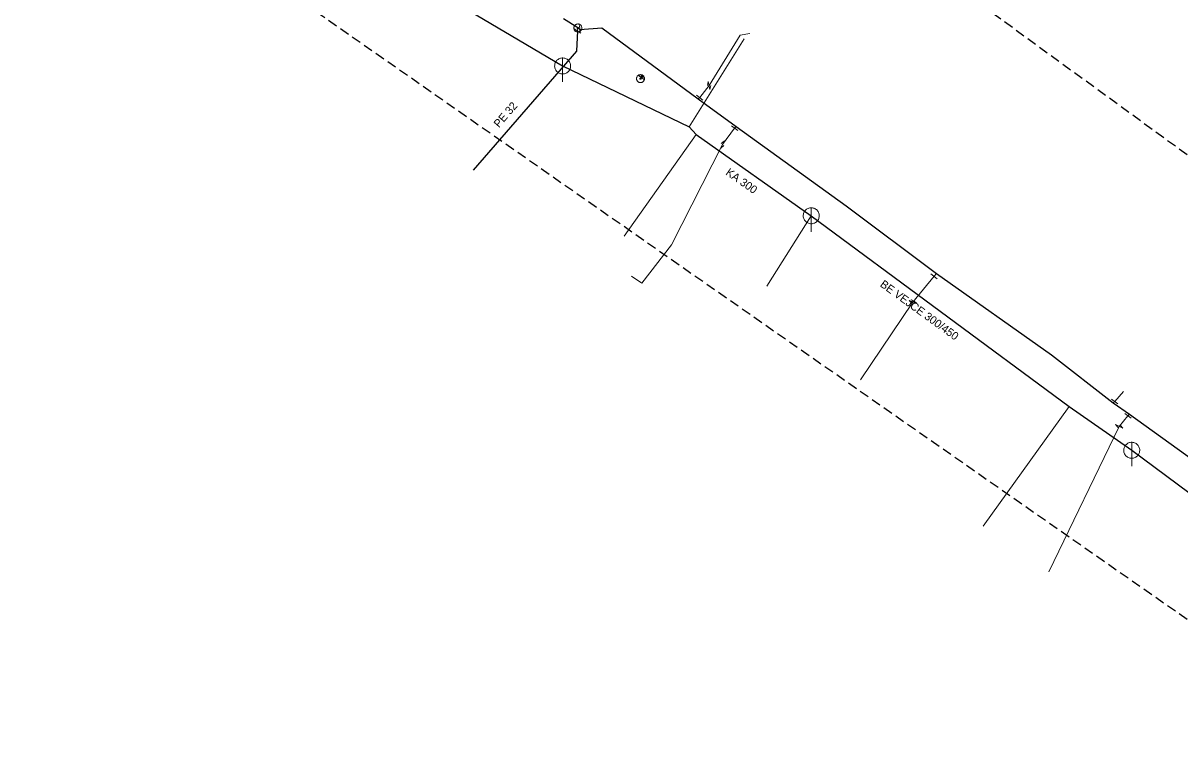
# Model space of a CAD drawing. Extents: x -749365 to -748625, y -965388 to -964881.
# Drawn here: x -748913.9 to -748769.4, y -965278.6 to -965189.7 of the extents above; entities that cross this region are included whole.
import ezdxf

# ---------------------------------------------------------------- set-up
doc = ezdxf.new("R2010")
doc.units = 0
doc.header["$LTSCALE"] = 0.4
doc.linetypes.add('MEDIUM_DASHED', pattern=[4.5, 3, -1.5])
for name, color, linetype, lineweight in [('1', 7, 'MEDIUM_DASHED', 25), ('11', 7, 'Continuous', 13), ('13', 7, 'Continuous', 13), ('14', 7, 'Continuous', 13), ('17', 7, 'Continuous', 25), ('22', 7, 'Continuous', 13), ('34', 7, 'Continuous', 13), ('47', 7, 'Continuous', 13), ('9', 7, 'Continuous', 13)]:
    doc.layers.add(name, color=color, linetype=linetype, lineweight=lineweight)

msp = doc.modelspace()

# ---------------------------------------------------------------- linework, layer by layer
at = {"layer": '1'}
for points in [[(-748843.645, -965151.367), (-748721.639, -965240.188)], [(-748747.771, -965278.626), (-748913.896, -965162.751)]]:
    msp.add_lwpolyline(points, dxfattribs=at)
at = {"layer": '11'}
for p, q in [((-748823.791, -965191.665), (-748830.686, -965202.653)), ((-748838.795, -965216.31), (-748829.791, -965203.589)), ((-748820.944, -965222.563), (-748815.417, -965213.762)), ((-748793.92, -965252.532), (-748783.169, -965237.599))]:
    msp.add_line(p, q, dxfattribs=at)
at = {"layer": '13'}
for p, q in [((-748829.35, -965198.989), (-748828.179, -965197.5)), ((-748824.986, -965202.824), (-748826.493, -965204.862)), ((-748800.07, -965221.322), (-748802.701, -965224.546)), ((-748802.701, -965224.546), (-748809.269, -965234.274)), ((-748777.5, -965236.96), (-748776.412, -965235.719)), ((-748775.84, -965238.756), (-748776.945, -965240.074)), ((-748776.945, -965240.074), (-748785.718, -965258.253))]:
    msp.add_line(p, q, dxfattribs=at)
for points in [[(-748828.179, -965197.5), (-748824.315, -965191.195), (-748823.096, -965190.973)], [(-748826.493, -965204.862), (-748832.894, -965217.38), (-748836.567, -965222.187), (-748837.857, -965221.327)]]:
    msp.add_lwpolyline(points, dxfattribs=at)
at = {"layer": '14', "lineweight": 25}
msp.add_line((-748900.66, -965162.96), (-748846.48, -965195.039), dxfattribs=at)
at = {"layer": '14'}
for p, q in [((-748844.578, -965190.3), (-748844.618, -965190.673)), ((-748844.578, -965190.3), (-748844.32, -965190.469)), ((-748836.754, -965196.63), (-748836.64, -965196.486)), ((-748836.64, -965196.486), (-748836.522, -965196.337)), ((-748829.535, -965199.166), (-748829.35, -965198.989)), ((-748824.8, -965202.6), (-748824.986, -965202.824)), ((-748799.78, -965220.98), (-748800.07, -965221.322)), ((-748777.69, -965237.149), (-748777.5, -965236.96)), ((-748775.66, -965238.539), (-748775.84, -965238.756))]:
    msp.add_line(p, q, dxfattribs=at)
at = {"layer": '14', "lineweight": 25}
for points in [[(-748846.48, -965195.039), (-748830.686, -965202.653), (-748829.791, -965203.589), (-748815.416, -965213.761)], [(-748815.416, -965213.761), (-748783.169, -965237.598), (-748775.37, -965243.07), (-748733.398, -965274.196)]]:
    msp.add_lwpolyline(points, dxfattribs=at)
at = {"layer": '17'}
msp.add_line((-748844.578, -965190.3), (-748846.378, -965189.157), dxfattribs=at)
for points in [[(-748844.618, -965190.673), (-748844.769, -965193.182), (-748857.681, -965208.058)], [(-748844.32, -965190.469), (-748841.57, -965190.28), (-748829.535, -965199.166), (-748824.8, -965202.6), (-748811.05, -965212.52), (-748799.78, -965220.98), (-748785.41, -965231.14), (-748777.69, -965237.149), (-748775.66, -965238.539), (-748746.309, -965259.66), (-748736.25, -965266.93)]]:
    msp.add_lwpolyline(points, dxfattribs=at)
at = {"layer": '22'}
for p, q in [((-748846.48, -965197.039), (-748846.479, -965194.039)), ((-748815.416, -965215.761), (-748815.415, -965212.761)), ((-748775.37, -965245.07), (-748775.369, -965242.07))]:
    msp.add_line(p, q, dxfattribs=at)
for points in [[(-748845.48, -965195.039), (-748845.485, -965194.93), (-748845.503, -965194.822), (-748845.533, -965194.716), (-748845.573, -965194.615), (-748845.625, -965194.518), (-748845.687, -965194.428), (-748845.759, -965194.345), (-748845.839, -965194.271), (-748845.927, -965194.205), (-748846.021, -965194.15), (-748846.121, -965194.105), (-748846.226, -965194.072), (-748846.333, -965194.05), (-748846.442, -965194.04), (-748846.552, -965194.042), (-748846.66, -965194.056), (-748846.767, -965194.081), (-748846.87, -965194.118), (-748846.968, -965194.167), (-748847.06, -965194.225), (-748847.146, -965194.294), (-748847.223, -965194.371), (-748847.292, -965194.457), (-748847.351, -965194.549), (-748847.399, -965194.647), (-748847.436, -965194.75), (-748847.462, -965194.857), (-748847.476, -965194.965), (-748847.479, -965195.075), (-748847.469, -965195.184), (-748847.448, -965195.291), (-748847.414, -965195.395), (-748847.37, -965195.495), (-748847.315, -965195.59), (-748847.249, -965195.678), (-748847.175, -965195.758), (-748847.092, -965195.83), (-748847.002, -965195.892), (-748846.906, -965195.944), (-748846.804, -965195.985), (-748846.699, -965196.015), (-748846.591, -965196.033), (-748846.481, -965196.039), (-748846.372, -965196.033), (-748846.264, -965196.015), (-748846.159, -965195.986), (-748846.057, -965195.945), (-748845.96, -965195.893), (-748845.87, -965195.831), (-748845.787, -965195.76), (-748845.712, -965195.68), (-748845.647, -965195.592), (-748845.591, -965195.498), (-748845.547, -965195.398), (-748845.513, -965195.294), (-748845.491, -965195.186), (-748845.481, -965195.077)], [(-748814.416, -965213.761), (-748814.421, -965213.652), (-748814.439, -965213.544), (-748814.469, -965213.438), (-748814.509, -965213.337), (-748814.561, -965213.24), (-748814.623, -965213.15), (-748814.695, -965213.067), (-748814.775, -965212.993), (-748814.863, -965212.927), (-748814.957, -965212.872), (-748815.057, -965212.827), (-748815.162, -965212.794), (-748815.269, -965212.772), (-748815.378, -965212.762), (-748815.488, -965212.764), (-748815.596, -965212.778), (-748815.703, -965212.803), (-748815.806, -965212.84), (-748815.904, -965212.889), (-748815.996, -965212.947), (-748816.082, -965213.016), (-748816.159, -965213.093), (-748816.228, -965213.179), (-748816.287, -965213.271), (-748816.335, -965213.369), (-748816.372, -965213.472), (-748816.398, -965213.579), (-748816.412, -965213.687), (-748816.415, -965213.797), (-748816.405, -965213.906), (-748816.384, -965214.013), (-748816.35, -965214.117), (-748816.306, -965214.217), (-748816.251, -965214.312), (-748816.185, -965214.4), (-748816.111, -965214.48), (-748816.028, -965214.552), (-748815.938, -965214.614), (-748815.842, -965214.666), (-748815.74, -965214.707), (-748815.635, -965214.737), (-748815.527, -965214.755), (-748815.417, -965214.761), (-748815.308, -965214.755), (-748815.2, -965214.737), (-748815.095, -965214.708), (-748814.993, -965214.667), (-748814.896, -965214.615), (-748814.806, -965214.553), (-748814.723, -965214.482), (-748814.648, -965214.402), (-748814.583, -965214.314), (-748814.527, -965214.22), (-748814.483, -965214.12), (-748814.449, -965214.016), (-748814.427, -965213.908), (-748814.417, -965213.799)], [(-748774.37, -965243.07), (-748774.375, -965242.961), (-748774.393, -965242.853), (-748774.423, -965242.747), (-748774.463, -965242.646), (-748774.515, -965242.549), (-748774.577, -965242.459), (-748774.649, -965242.376), (-748774.729, -965242.302), (-748774.817, -965242.236), (-748774.911, -965242.181), (-748775.011, -965242.136), (-748775.116, -965242.103), (-748775.223, -965242.081), (-748775.332, -965242.071), (-748775.442, -965242.073), (-748775.55, -965242.087), (-748775.657, -965242.112), (-748775.76, -965242.149), (-748775.858, -965242.198), (-748775.95, -965242.256), (-748776.036, -965242.325), (-748776.113, -965242.402), (-748776.182, -965242.488), (-748776.241, -965242.58), (-748776.289, -965242.678), (-748776.326, -965242.781), (-748776.352, -965242.888), (-748776.366, -965242.996), (-748776.369, -965243.106), (-748776.359, -965243.215), (-748776.338, -965243.322), (-748776.304, -965243.426), (-748776.26, -965243.526), (-748776.205, -965243.621), (-748776.139, -965243.709), (-748776.065, -965243.789), (-748775.982, -965243.861), (-748775.892, -965243.923), (-748775.796, -965243.975), (-748775.694, -965244.016), (-748775.589, -965244.046), (-748775.481, -965244.064), (-748775.371, -965244.07), (-748775.262, -965244.064), (-748775.154, -965244.046), (-748775.049, -965244.017), (-748774.947, -965243.976), (-748774.85, -965243.924), (-748774.76, -965243.862), (-748774.677, -965243.791), (-748774.602, -965243.711), (-748774.537, -965243.623), (-748774.481, -965243.529), (-748774.437, -965243.429), (-748774.403, -965243.325), (-748774.381, -965243.217), (-748774.371, -965243.108)]]:
    msp.add_lwpolyline(points, close=True, dxfattribs=at)
at = {"layer": '34'}
for p, q in [((-748844.203, -965190.952), (-748845.032, -965190.392)), ((-748844.354, -965189.97), (-748844.286, -965190.967)), ((-748837.042, -965196.188), (-748836.238, -965196.783)), ((-748829.743, -965198.68), (-748828.957, -965199.298)), ((-748824.583, -965203.12), (-748825.387, -965202.526)), ((-748799.682, -965221.637), (-748800.457, -965221.005)), ((-748777.905, -965236.667), (-748777.094, -965237.252)), ((-748775.432, -965239.045), (-748776.246, -965238.465))]:
    msp.add_line(p, q, dxfattribs=at)
at = {"layer": '47'}
for p, q in [((-748828.277, -965197), (-748828.38, -965197.5)), ((-748826.27, -965204.403), (-748826.653, -965204.741)), ((-748802.231, -965224.744), (-748802.588, -965224.379)), ((-748776.499, -965240.32), (-748776.815, -965239.92))]:
    msp.add_line(p, q, dxfattribs=at)
for points in [[(-748844.857, -965190.714), (-748844.813, -965190.74), (-748844.765, -965190.763), (-748844.716, -965190.779), (-748844.665, -965190.792), (-748844.613, -965190.798), (-748844.56, -965190.799), (-748844.508, -965190.794), (-748844.457, -965190.784), (-748844.407, -965190.769), (-748844.359, -965190.749), (-748844.312, -965190.724), (-748844.27, -965190.693), (-748844.231, -965190.659), (-748844.195, -965190.621), (-748844.163, -965190.579), (-748844.137, -965190.535), (-748844.114, -965190.487), (-748844.097, -965190.437), (-748844.085, -965190.387), (-748844.079, -965190.335), (-748844.078, -965190.282), (-748844.083, -965190.23), (-748844.092, -965190.178), (-748844.107, -965190.128), (-748844.128, -965190.081), (-748844.153, -965190.034), (-748844.183, -965189.991), (-748844.218, -965189.953), (-748844.256, -965189.917), (-748844.298, -965189.885), (-748844.342, -965189.859), (-748844.39, -965189.836), (-748844.439, -965189.818), (-748844.49, -965189.807), (-748844.542, -965189.801), (-748844.594, -965189.799), (-748844.647, -965189.804), (-748844.698, -965189.814), (-748844.749, -965189.829), (-748844.796, -965189.85), (-748844.843, -965189.875), (-748844.885, -965189.905), (-748844.924, -965189.94), (-748844.96, -965189.978), (-748844.992, -965190.02), (-748845.018, -965190.064), (-748845.041, -965190.112), (-748845.058, -965190.161), (-748845.07, -965190.212), (-748845.076, -965190.264), (-748845.078, -965190.316), (-748845.073, -965190.368), (-748845.063, -965190.419), (-748845.047, -965190.47), (-748845.027, -965190.518), (-748845.002, -965190.565), (-748844.972, -965190.606), (-748844.937, -965190.646), (-748844.899, -965190.682)], [(-748844.623, -965190.367), (-748844.616, -965190.372), (-748844.608, -965190.375), (-748844.6, -965190.378), (-748844.592, -965190.38), (-748844.583, -965190.381), (-748844.575, -965190.381), (-748844.566, -965190.381), (-748844.558, -965190.379), (-748844.55, -965190.376), (-748844.542, -965190.373), (-748844.534, -965190.369), (-748844.527, -965190.364), (-748844.521, -965190.358), (-748844.515, -965190.353), (-748844.51, -965190.345), (-748844.505, -965190.338), (-748844.502, -965190.33), (-748844.499, -965190.322), (-748844.497, -965190.314), (-748844.496, -965190.305), (-748844.496, -965190.297), (-748844.496, -965190.288), (-748844.498, -965190.28), (-748844.5, -965190.271), (-748844.504, -965190.264), (-748844.508, -965190.256), (-748844.513, -965190.249), (-748844.519, -965190.243), (-748844.524, -965190.237), (-748844.532, -965190.232), (-748844.539, -965190.227), (-748844.547, -965190.224), (-748844.555, -965190.221), (-748844.563, -965190.219), (-748844.572, -965190.218), (-748844.58, -965190.217), (-748844.589, -965190.218), (-748844.597, -965190.22), (-748844.606, -965190.222), (-748844.613, -965190.226), (-748844.621, -965190.23), (-748844.628, -965190.235), (-748844.634, -965190.241), (-748844.64, -965190.246), (-748844.645, -965190.254), (-748844.65, -965190.261), (-748844.653, -965190.269), (-748844.656, -965190.277), (-748844.658, -965190.285), (-748844.659, -965190.294), (-748844.66, -965190.302), (-748844.659, -965190.311), (-748844.657, -965190.319), (-748844.654, -965190.327), (-748844.651, -965190.335), (-748844.647, -965190.343), (-748844.642, -965190.35), (-748844.636, -965190.356), (-748844.631, -965190.362)], [(-748836.35, -965196.925), (-748836.322, -965196.881), (-748836.297, -965196.834), (-748836.279, -965196.786), (-748836.265, -965196.736), (-748836.256, -965196.683), (-748836.254, -965196.631), (-748836.257, -965196.579), (-748836.265, -965196.527), (-748836.278, -965196.477), (-748836.296, -965196.428), (-748836.32, -965196.381), (-748836.349, -965196.337), (-748836.381, -965196.296), (-748836.418, -965196.259), (-748836.458, -965196.226), (-748836.502, -965196.198), (-748836.549, -965196.173), (-748836.598, -965196.155), (-748836.647, -965196.141), (-748836.7, -965196.132), (-748836.752, -965196.13), (-748836.805, -965196.132), (-748836.856, -965196.14), (-748836.907, -965196.153), (-748836.955, -965196.172), (-748837.002, -965196.196), (-748837.047, -965196.224), (-748837.087, -965196.257), (-748837.124, -965196.294), (-748837.157, -965196.334), (-748837.185, -965196.378), (-748837.21, -965196.425), (-748837.229, -965196.474), (-748837.242, -965196.523), (-748837.251, -965196.576), (-748837.254, -965196.628), (-748837.252, -965196.68), (-748837.244, -965196.732), (-748837.23, -965196.783), (-748837.211, -965196.831), (-748837.187, -965196.878), (-748837.16, -965196.922), (-748837.126, -965196.963), (-748837.089, -965197), (-748837.049, -965197.033), (-748837.005, -965197.061), (-748836.958, -965197.086), (-748836.91, -965197.105), (-748836.86, -965197.118), (-748836.807, -965197.127), (-748836.755, -965197.13), (-748836.704, -965197.127), (-748836.652, -965197.119), (-748836.601, -965197.105), (-748836.552, -965197.087), (-748836.505, -965197.063), (-748836.462, -965197.035), (-748836.42, -965197.002), (-748836.383, -965196.965)], [(-748836.687, -965196.678), (-748836.682, -965196.671), (-748836.679, -965196.663), (-748836.676, -965196.655), (-748836.673, -965196.647), (-748836.672, -965196.638), (-748836.672, -965196.63), (-748836.672, -965196.621), (-748836.673, -965196.613), (-748836.676, -965196.605), (-748836.678, -965196.596), (-748836.683, -965196.588), (-748836.687, -965196.581), (-748836.693, -965196.575), (-748836.698, -965196.569), (-748836.705, -965196.563), (-748836.712, -965196.558), (-748836.72, -965196.555), (-748836.728, -965196.552), (-748836.736, -965196.549), (-748836.745, -965196.548), (-748836.753, -965196.548), (-748836.762, -965196.548), (-748836.77, -965196.549), (-748836.779, -965196.551), (-748836.787, -965196.554), (-748836.795, -965196.559), (-748836.802, -965196.563), (-748836.808, -965196.569), (-748836.814, -965196.574), (-748836.82, -965196.581), (-748836.825, -965196.588), (-748836.828, -965196.596), (-748836.831, -965196.604), (-748836.834, -965196.612), (-748836.835, -965196.621), (-748836.836, -965196.629), (-748836.835, -965196.638), (-748836.834, -965196.646), (-748836.832, -965196.655), (-748836.829, -965196.663), (-748836.824, -965196.671), (-748836.82, -965196.678), (-748836.814, -965196.684), (-748836.809, -965196.69), (-748836.802, -965196.696), (-748836.795, -965196.701), (-748836.787, -965196.704), (-748836.779, -965196.707), (-748836.771, -965196.71), (-748836.762, -965196.711), (-748836.754, -965196.712), (-748836.745, -965196.711), (-748836.737, -965196.71), (-748836.729, -965196.707), (-748836.72, -965196.705), (-748836.712, -965196.7), (-748836.705, -965196.696), (-748836.699, -965196.69), (-748836.693, -965196.685)]]:
    msp.add_lwpolyline(points, close=True, dxfattribs=at)
for points in [[(-748828.277, -965197), (-748828.081, -965198), (-748827.978, -965197.5)], [(-748826.27, -965204.403), (-748826.715, -965205.32), (-748826.332, -965204.982)], [(-748802.231, -965224.744), (-748803.17, -965224.347), (-748802.813, -965224.712)], [(-748776.499, -965240.32), (-748777.39, -965239.827), (-748777.074, -965240.227)]]:
    msp.add_lwpolyline(points, dxfattribs=at)
at = {"layer": '9'}
for points in [[(-748836.648, -965196.337), (-748836.648, -965196.35), (-748836.646, -965196.363), (-748836.643, -965196.376), (-748836.638, -965196.388), (-748836.632, -965196.4), (-748836.625, -965196.411), (-748836.617, -965196.421), (-748836.607, -965196.431), (-748836.597, -965196.439), (-748836.586, -965196.446), (-748836.574, -965196.452), (-748836.562, -965196.457), (-748836.549, -965196.46), (-748836.536, -965196.462), (-748836.523, -965196.464), (-748836.51, -965196.463), (-748836.497, -965196.461), (-748836.484, -965196.458), (-748836.472, -965196.453), (-748836.46, -965196.447), (-748836.449, -965196.44), (-748836.439, -965196.432), (-748836.429, -965196.422), (-748836.421, -965196.412), (-748836.414, -965196.401), (-748836.408, -965196.389), (-748836.403, -965196.377), (-748836.4, -965196.364), (-748836.398, -965196.351), (-748836.396, -965196.338), (-748836.397, -965196.325), (-748836.399, -965196.312), (-748836.402, -965196.299), (-748836.407, -965196.287), (-748836.413, -965196.275), (-748836.42, -965196.264), (-748836.428, -965196.254), (-748836.438, -965196.244), (-748836.448, -965196.236), (-748836.459, -965196.229), (-748836.471, -965196.223), (-748836.483, -965196.218), (-748836.496, -965196.215), (-748836.509, -965196.213), (-748836.522, -965196.212), (-748836.535, -965196.212), (-748836.548, -965196.214), (-748836.561, -965196.217), (-748836.573, -965196.222), (-748836.585, -965196.228), (-748836.596, -965196.235), (-748836.606, -965196.243), (-748836.616, -965196.253), (-748836.624, -965196.263), (-748836.631, -965196.274), (-748836.637, -965196.286), (-748836.642, -965196.298), (-748836.645, -965196.311), (-748836.647, -965196.324)], [(-748836.628, -965196.337), (-748836.629, -965196.348), (-748836.627, -965196.359), (-748836.624, -965196.37), (-748836.62, -965196.38), (-748836.615, -965196.39), (-748836.609, -965196.399), (-748836.602, -965196.408), (-748836.594, -965196.416), (-748836.585, -965196.423), (-748836.576, -965196.429), (-748836.566, -965196.434), (-748836.556, -965196.438), (-748836.545, -965196.441), (-748836.534, -965196.444), (-748836.523, -965196.444), (-748836.512, -965196.444), (-748836.501, -965196.442), (-748836.49, -965196.439), (-748836.48, -965196.435), (-748836.47, -965196.43), (-748836.461, -965196.424), (-748836.452, -965196.417), (-748836.444, -965196.409), (-748836.437, -965196.4), (-748836.431, -965196.391), (-748836.426, -965196.381), (-748836.422, -965196.371), (-748836.419, -965196.36), (-748836.417, -965196.349), (-748836.416, -965196.338), (-748836.416, -965196.327), (-748836.418, -965196.316), (-748836.421, -965196.305), (-748836.425, -965196.295), (-748836.43, -965196.285), (-748836.436, -965196.276), (-748836.443, -965196.267), (-748836.451, -965196.259), (-748836.46, -965196.252), (-748836.469, -965196.246), (-748836.479, -965196.241), (-748836.489, -965196.237), (-748836.5, -965196.234), (-748836.511, -965196.232), (-748836.522, -965196.232), (-748836.533, -965196.231), (-748836.544, -965196.233), (-748836.555, -965196.236), (-748836.565, -965196.24), (-748836.575, -965196.245), (-748836.584, -965196.251), (-748836.593, -965196.258), (-748836.601, -965196.266), (-748836.608, -965196.275), (-748836.614, -965196.284), (-748836.619, -965196.294), (-748836.623, -965196.304), (-748836.626, -965196.315), (-748836.628, -965196.326)], [(-748836.609, -965196.337), (-748836.609, -965196.346), (-748836.608, -965196.355), (-748836.605, -965196.364), (-748836.602, -965196.372), (-748836.598, -965196.38), (-748836.593, -965196.388), (-748836.587, -965196.395), (-748836.581, -965196.401), (-748836.574, -965196.407), (-748836.566, -965196.412), (-748836.558, -965196.416), (-748836.55, -965196.419), (-748836.541, -965196.422), (-748836.532, -965196.423), (-748836.523, -965196.425), (-748836.514, -965196.424), (-748836.505, -965196.423), (-748836.496, -965196.42), (-748836.488, -965196.417), (-748836.48, -965196.413), (-748836.472, -965196.408), (-748836.465, -965196.402), (-748836.459, -965196.396), (-748836.453, -965196.389), (-748836.448, -965196.381), (-748836.444, -965196.373), (-748836.441, -965196.365), (-748836.438, -965196.356), (-748836.437, -965196.347), (-748836.434, -965196.338), (-748836.436, -965196.329), (-748836.437, -965196.32), (-748836.44, -965196.311), (-748836.443, -965196.303), (-748836.447, -965196.295), (-748836.452, -965196.287), (-748836.458, -965196.28), (-748836.464, -965196.274), (-748836.471, -965196.268), (-748836.479, -965196.263), (-748836.487, -965196.259), (-748836.495, -965196.256), (-748836.504, -965196.253), (-748836.513, -965196.252), (-748836.522, -965196.251), (-748836.531, -965196.251), (-748836.54, -965196.252), (-748836.549, -965196.255), (-748836.557, -965196.258), (-748836.565, -965196.262), (-748836.573, -965196.267), (-748836.58, -965196.273), (-748836.586, -965196.279), (-748836.592, -965196.286), (-748836.597, -965196.294), (-748836.601, -965196.302), (-748836.604, -965196.31), (-748836.607, -965196.319), (-748836.608, -965196.328)], [(-748836.589, -965196.337), (-748836.589, -965196.344), (-748836.588, -965196.351), (-748836.587, -965196.358), (-748836.584, -965196.364), (-748836.581, -965196.37), (-748836.577, -965196.376), (-748836.573, -965196.382), (-748836.568, -965196.387), (-748836.562, -965196.391), (-748836.556, -965196.395), (-748836.55, -965196.398), (-748836.544, -965196.401), (-748836.537, -965196.402), (-748836.53, -965196.405), (-748836.523, -965196.405), (-748836.516, -965196.405), (-748836.509, -965196.403), (-748836.502, -965196.402), (-748836.496, -965196.399), (-748836.489, -965196.396), (-748836.484, -965196.392), (-748836.478, -965196.388), (-748836.473, -965196.383), (-748836.469, -965196.377), (-748836.465, -965196.371), (-748836.462, -965196.365), (-748836.459, -965196.359), (-748836.457, -965196.352), (-748836.456, -965196.345), (-748836.455, -965196.338), (-748836.455, -965196.331), (-748836.456, -965196.324), (-748836.458, -965196.317), (-748836.461, -965196.311), (-748836.464, -965196.304), (-748836.468, -965196.299), (-748836.472, -965196.293), (-748836.477, -965196.288), (-748836.483, -965196.284), (-748836.488, -965196.28), (-748836.495, -965196.277), (-748836.501, -965196.274), (-748836.508, -965196.272), (-748836.515, -965196.271), (-748836.522, -965196.271), (-748836.529, -965196.271), (-748836.536, -965196.271), (-748836.543, -965196.273), (-748836.549, -965196.276), (-748836.555, -965196.279), (-748836.561, -965196.283), (-748836.567, -965196.287), (-748836.572, -965196.292), (-748836.576, -965196.298), (-748836.58, -965196.303), (-748836.583, -965196.31), (-748836.586, -965196.316), (-748836.587, -965196.323), (-748836.589, -965196.33)], [(-748836.569, -965196.337), (-748836.569, -965196.342), (-748836.569, -965196.347), (-748836.568, -965196.352), (-748836.566, -965196.356), (-748836.564, -965196.361), (-748836.561, -965196.365), (-748836.558, -965196.368), (-748836.554, -965196.372), (-748836.551, -965196.375), (-748836.547, -965196.378), (-748836.542, -965196.38), (-748836.538, -965196.382), (-748836.533, -965196.383), (-748836.528, -965196.385), (-748836.523, -965196.385), (-748836.518, -965196.385), (-748836.513, -965196.384), (-748836.508, -965196.383), (-748836.504, -965196.381), (-748836.499, -965196.379), (-748836.495, -965196.376), (-748836.491, -965196.373), (-748836.488, -965196.369), (-748836.485, -965196.366), (-748836.482, -965196.362), (-748836.48, -965196.357), (-748836.478, -965196.353), (-748836.477, -965196.348), (-748836.476, -965196.343), (-748836.475, -965196.338), (-748836.475, -965196.333), (-748836.476, -965196.328), (-748836.477, -965196.323), (-748836.479, -965196.319), (-748836.481, -965196.314), (-748836.484, -965196.31), (-748836.487, -965196.306), (-748836.49, -965196.303), (-748836.494, -965196.3), (-748836.498, -965196.297), (-748836.503, -965196.295), (-748836.507, -965196.293), (-748836.512, -965196.292), (-748836.517, -965196.291), (-748836.522, -965196.291), (-748836.527, -965196.291), (-748836.532, -965196.292), (-748836.537, -965196.292), (-748836.541, -965196.294), (-748836.546, -965196.296), (-748836.55, -965196.299), (-748836.553, -965196.302), (-748836.557, -965196.305), (-748836.559, -965196.309), (-748836.563, -965196.313), (-748836.565, -965196.318), (-748836.567, -965196.322), (-748836.568, -965196.327), (-748836.569, -965196.332)], [(-748836.549, -965196.337), (-748836.549, -965196.34), (-748836.55, -965196.343), (-748836.549, -965196.345), (-748836.548, -965196.348), (-748836.547, -965196.351), (-748836.545, -965196.353), (-748836.543, -965196.355), (-748836.541, -965196.357), (-748836.539, -965196.359), (-748836.537, -965196.361), (-748836.534, -965196.363), (-748836.531, -965196.364), (-748836.529, -965196.364), (-748836.526, -965196.365), (-748836.523, -965196.365), (-748836.52, -965196.365), (-748836.517, -965196.365), (-748836.514, -965196.364), (-748836.512, -965196.363), (-748836.509, -965196.362), (-748836.507, -965196.36), (-748836.504, -965196.358), (-748836.502, -965196.356), (-748836.501, -965196.354), (-748836.499, -965196.352), (-748836.498, -965196.349), (-748836.496, -965196.346), (-748836.496, -965196.344), (-748836.495, -965196.341), (-748836.494, -965196.338), (-748836.495, -965196.335), (-748836.495, -965196.332), (-748836.496, -965196.329), (-748836.497, -965196.327), (-748836.498, -965196.324), (-748836.5, -965196.322), (-748836.501, -965196.319), (-748836.503, -965196.317), (-748836.506, -965196.316), (-748836.508, -965196.314), (-748836.511, -965196.313), (-748836.513, -965196.312), (-748836.516, -965196.311), (-748836.519, -965196.311), (-748836.522, -965196.31), (-748836.525, -965196.311), (-748836.528, -965196.31), (-748836.53, -965196.312), (-748836.533, -965196.312), (-748836.536, -965196.313), (-748836.538, -965196.315), (-748836.54, -965196.316), (-748836.542, -965196.318), (-748836.544, -965196.321), (-748836.546, -965196.323), (-748836.547, -965196.326), (-748836.548, -965196.328), (-748836.549, -965196.331), (-748836.549, -965196.334)], [(-748836.53, -965196.337), (-748836.53, -965196.339), (-748836.53, -965196.339), (-748836.529, -965196.339), (-748836.529, -965196.341), (-748836.53, -965196.342), (-748836.528, -965196.342), (-748836.528, -965196.342), (-748836.528, -965196.344), (-748836.528, -965196.344), (-748836.527, -965196.345), (-748836.525, -965196.345), (-748836.525, -965196.345), (-748836.525, -965196.346), (-748836.523, -965196.346), (-748836.523, -965196.346), (-748836.522, -965196.346), (-748836.521, -965196.346), (-748836.521, -965196.345), (-748836.52, -965196.345), (-748836.518, -965196.345), (-748836.518, -965196.344), (-748836.518, -965196.344), (-748836.517, -965196.343), (-748836.517, -965196.343), (-748836.515, -965196.342), (-748836.515, -965196.341), (-748836.514, -965196.34), (-748836.514, -965196.34), (-748836.514, -965196.339), (-748836.514, -965196.338), (-748836.514, -965196.337), (-748836.514, -965196.336), (-748836.514, -965196.336), (-748836.515, -965196.335), (-748836.515, -965196.334), (-748836.516, -965196.333), (-748836.516, -965196.333), (-748836.517, -965196.332), (-748836.517, -965196.332), (-748836.518, -965196.331), (-748836.519, -965196.331), (-748836.52, -965196.33), (-748836.52, -965196.33), (-748836.521, -965196.33), (-748836.522, -965196.33), (-748836.523, -965196.33), (-748836.524, -965196.33), (-748836.524, -965196.33), (-748836.525, -965196.331), (-748836.526, -965196.33), (-748836.527, -965196.332), (-748836.527, -965196.332), (-748836.528, -965196.332), (-748836.528, -965196.332), (-748836.529, -965196.334), (-748836.529, -965196.335), (-748836.529, -965196.336), (-748836.53, -965196.336), (-748836.53, -965196.337)]]:
    msp.add_lwpolyline(points, close=True, dxfattribs=at)

# ---------------------------------------------------------------- texts
at = {"layer": '1'}
for s, rotation, p in [('PE 32 ', 49, (-748854.444, -965202.825)), ('KA 300', 325, (-748826.199, -965208.562)), ('BE VEJCE 300/450', 324, (-748806.905, -965222.52))]:
    msp.add_text(s, height=1, rotation=rotation, dxfattribs=at).set_placement(p)

doc.saveas('drawing.dxf')
